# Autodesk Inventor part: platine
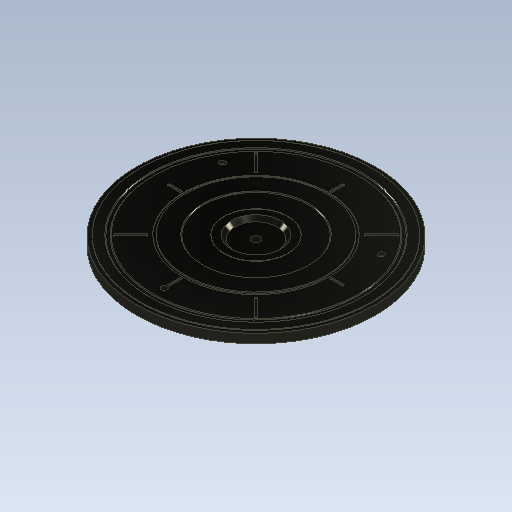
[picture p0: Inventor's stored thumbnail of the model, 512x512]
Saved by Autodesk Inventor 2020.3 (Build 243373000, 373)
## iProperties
Created: 2020-09
Part Number: platine
Material: Plastique ABS
Document SubType Name: Modeling
Designer: ficho
Density: 1.06 g/cm^3
Appearance: Vert-de-gris
Mass: 110.602 g
Surface Area: 867.228 cm^2
Volume: 104.342 cm^3
Author: ficho
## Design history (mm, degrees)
sketch "Esquisse1"
  geometry: L1 (3.5, 0)-(6, 0); L2 (99, 22.5)-(99, 30); L3 (3.5, 27.668)-(3.5, 0); L4 (37.435, 0)-(29.985, 0); L5 (65, 14)-(65, 28); L6 (65, 28)-(96, 28); L7 (65, 14)-(63, 14); L8 (6, 6.14)-(6, 0); L9 (96, 28)-(96, 22.5); L10 (96, 22.5)-(99, 22.5); L11 (6, 25.668)-(19.293, 25.668); L12 (63, 25.668)-(63, 14); L13 (6, 6.14)-(6, 25.668); L14 (43.5, 30.368)-(43.5, 30.968); L15 (96, 30.6)-(96, 30); L16 (88, 30.6)-(88, 30); L17 (85.5, 30.6)-(85.5, 30); L18 (60.5, 30.6)-(60.5, 30); L19 (58.5, 30.968)-(58.5, 30); L20 (43.5, 30.968)-(58.5, 30.968); L21 (60.5, 30.6)-(85.5, 30.6); L22 (88, 30.6)-(96, 30.6); L23 (60.5, 30)-(58.5, 30); L24 (88, 30)-(85.5, 30); L25 (60.5, 30)-(58.5, 30); L26 (99, 30)-(96, 30); L27 (88, 30)-(85.5, 30); L28 (17.5, 30)-(17.5, 30.668); L29 (17.5, 30.668)-(26.5, 30.668); L30 (26.5, 30.668)-(26.5, 30.368); L31 (43.5, 30.368)-(26.5, 30.368); L32 (3.5, 27.668)-(17.5, 27.668); L33 (17.5, 27.668)-(17.5, 30); L34 (19.293, 25.668)-(19.293, 27.018); L35 (42, 28.368)-(63, 28.368); L36 (63, 28.368)-(63, 25.668); L37 (19.293, 27.018)-(42, 27.018); L38 (42, 27.018)-(42, 28.368); L39 (0, -6.194)-(0, 37.162) reference; 2 further points
  constraints: 76 end point, 16 parallel, 13 perpendicular, 7 horizontal, 2 vertical, 1 collinear
  dimensions: "d0" = 3.5 distance from line of L3 point (0, 0); "d1" = 6 distance from line of point (0, 0) L8; "d2" = 63 distance from line of point (0, 0) L12; "d3" = 65 distance from line of point (0, 0) L5; "d4" = 99 distance from line of L2 point (0, 0); "d5" = 31 distance between parallel lines of L9 L5; "d9" = 0.6 distance of L14.start L14.end; "d10" = 3 distance between parallel lines of L2 L15; "d11" = 8 distance between parallel lines of L16 L15; "d12" = 2.5 distance between parallel lines of L16 L17; "d13" = 25 distance between parallel lines of L18 L17; "d14" = 2 distance between parallel lines of L18 L19; "d15" = 15 distance between parallel lines of L19 L14; "d18" = 17 distance between parallel lines of L14 L30; "d19" = 3 distance between parallel lines of L32 L29; "d20" = 0.3 distance between parallel lines of L29 L31; "d21" = 30 distance from line of point (0, 0) L26; "d22" = 2 distance between parallel lines of L32 L11; "d23" = 2 distance between parallel lines of L35 L31; "d24" = 16 distance between parallel lines of L26 L7; "d25" = 42 distance from line of L38 point (0, 0)
revolve "Révolution1" sketch "Esquisse1" stored, may be unused: angle "d26" = 90 deg
sketch "Esquisse2"
  geometry: 2 further points
  dimensions: "d27" = 76 distance of point (0, -76) point (0, 0)
hole "Perçage1" sketch "Esquisse2" at (0, -76) diameter "d28" = 5; stored, may be unused: countersink angle "d32" = 90 deg, drill point angle "d34" = 118 deg; dims "d29" = 10, "d30" = 4, "d31" = 2, "d33" = 14.2
sketch "Esquisse3"
  geometry: L1 (1, -61.5)-(-1, -61.5); L2 (-1, -61.5)-(-1, -72.5); L3 (-1, -72.5)-(1, -72.5); L4 (1, -72.5)-(1, -61.5); 1 further point
  constraints: 8 end point, 2 parallel, 1 horizontal, 1 perpendicular
  dimensions: "d38" = 11 distance between parallel lines of L3 L1; "d39" = 2 distance between parallel lines of L2 L4; "d40" = 1 distance from line of point (0, 0) L2; "d41" = 61.5 distance from line of point (0, 0) L1
extrude "Extrusion1" cut sketch "Esquisse3" distance "d42" = 1; taper "d43" = 0 deg
pattern_circular "Réseau circulaire2" dims angle "d45" = 360 deg
pattern_circular "Réseau circulaire3" dims angle "d48" = 360 deg
sketch "Esquisse5"
  geometry: L1 (44.082, -45.496)-(58.224, -59.638); L2 (58.224, -59.638)-(59.638, -58.224); L3 (59.638, -58.224)-(45.496, -44.082); L4 (45.496, -44.082)-(44.082, -45.496); L5 (44.082, -45.496)-(59.638, -58.224); L6 (44.082, -45.496)-(64.082, -45.496); L7 (72.5, -1)-(61.5, -1) reference; L8 (1, -61.5)-(1, -72.5) reference; L9 (0, 0)-(103.816, 0); L10 (44.789, -44.789)-(45.496, -45.496); L11 (58.224, -59.638)-(51.86, -51.86); L12 (46.653, -45.496)-(45.496, -44.082); 1 further point
  constraints: 20 end point, 3 midpoint, 2 horizontal, 2 parallel, 2 point on line, 1 equal length, 1 perpendicular
  dimensions: "d51" = 20 distance of L1.start L1.end; "d53" = 2 distance of L2.end L1.end
extrude "Extrusion2" cut sketch "Esquisse5" distance "d58" = 1; taper "d59" = 0 deg
pattern_circular "Réseau circulaire4" dims angle "d61" = 360 deg
sketch "Esquisse6"
  geometry: L1 (41.5, -1)-(3.77, -1); L2 (3.77, -1)-(3.77, 1); L3 (3.77, 1)-(41.5, 1); L4 (41.5, 1)-(41.5, -1); 1 further point
  constraints: 8 end point, 2 parallel, 1 horizontal, 1 perpendicular
  dimensions: "d63" = 1 distance from line of L3 point (0, 0); "d64" = 1 distance from line of L1 point (0, 0) (= d63); "d65" = 41.5 distance from line of point (0, 0) L4
extrude "Extrusion3" join sketch "Esquisse6" distance "d66" = 10; taper "d67" = 0 deg
pattern_circular "Réseau circulaire5" dims angle "d69" = 360 deg
sketch "Esquisse7"
  geometry: L1 (27.018, 41.5)-(17.018, 41.5) reference; L2 (22.798, 47.068)-(17.018, 5.762); L3 (17.018, 5.762)-(17.018, 41.5); L4 (14, 65)-(14, -65) reference; L5 (-5.404, 0)-(32.422, 0) reference; L6 (17.018, 41.5)-(17.018, 47.068); L7 (17.018, 47.068)-(22.798, 47.068); 4 further points
  constraints: 8 end point, 1 midpoint, 1 parallel, 1 perpendicular, 1 point on line, 1 vertical
revolve "Révolution2" sketch "Esquisse7" stored, may be unused: angle "d71" = 90 deg
chamfer "Chanfrein1" distance "d72" = 3; stored, may be unused: second distance "d73" = 2, angle "d74" = 45 deg
chamfer "Chanfrein2" distance "d75" = 0.6; stored, may be unused: second distance "d76" = 2, angle "d77" = 45 deg
chamfer "Chanfrein3" distance "d78" = 0.6; stored, may be unused: second distance "d79" = 2, angle "d80" = 45 deg
node "Solide1"
other parameters: "d7" = 2, "d8" = 7.5, "d56" = 45 deg, "d57" = 1
